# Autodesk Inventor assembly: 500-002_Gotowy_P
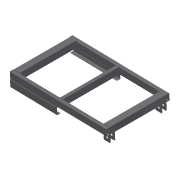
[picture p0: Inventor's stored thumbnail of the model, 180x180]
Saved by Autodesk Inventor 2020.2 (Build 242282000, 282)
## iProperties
Created: 2016-09
Part Number: 500-002_Gotowy_P
Document SubType Name: Assembly
Designer: F.Stasiak
Description: Stół
Manager: www.cadconsulting.pl
Company: Fabian Stasiak CAD Consulting
Author: F.Stasiak
Subject: Zbiór ćwiczeń. Autodesk Inventor 2020. Kurs podstawowy
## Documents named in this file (10)
- C:\2020_Kurs_podstawowy\R6 Zespoły\Warsztat\Komponenty\500-002_Gotowy_P.iam
- C:\2020_Kurs_podstawowy\R6 Zespoły\Warsztat\Komponenty\500-01-07.ipt
- C:\2020_Kurs_podstawowy\R6 Zespoły\Warsztat\Komponenty\500-01-06.ipt
- C:\2020_Kurs_podstawowy\R6 Zespoły\Warsztat\Komponenty\EN 10058 - 500-01-08.ipt
- C:\2020_Kurs_podstawowy\R6 Zespoły\Warsztat\Komponenty\DIN 120x60x4 500-01-01.ipt
- DIN 120x60x4 900-01-1.ipt
- C:\2020_Kurs_podstawowy\R6 Zespoły\Warsztat\Komponenty\DIN 120x60x4 500-01-04.ipt
- DIN 120x60x4 900-01-04.ipt
- C:\2020_Kurs_podstawowy\R6 Zespoły\Warsztat\Komponenty\DIN 120x60x4 500-01-02.ipt
- DIN 120x60x4 900-01-02.ipt
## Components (13 placed, 6 different names)
1. 500-01-07:1
2. 500-01-07:2
3. 500-01-07:3 — Sztywne:12
4. 500-01-07:4 — Sztywne:10
5. 500-01-06:1
6. 500-01-06:2
7. EN 10058 - 500-01-08:1
8. EN 10058 - 500-01-08:2
9. DIN 120x60x4 500-01-01:3
10. DIN 120x60x4 500-01-01:4
11. DIN 120x60x4 500-01-04:3 — Sztywne:10, Sztywne:12
12. DIN 120x60x4 500-01-04:4
13. DIN 120x60x4 500-01-02:2
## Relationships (2: WeldJoint 2)
- Sztywne:10 [WeldJoint]: 500-01-07:4 ↔ DIN 120x60x4 500-01-04:3
- Sztywne:12 [WeldJoint]: 500-01-07:3 ↔ DIN 120x60x4 500-01-04:3
